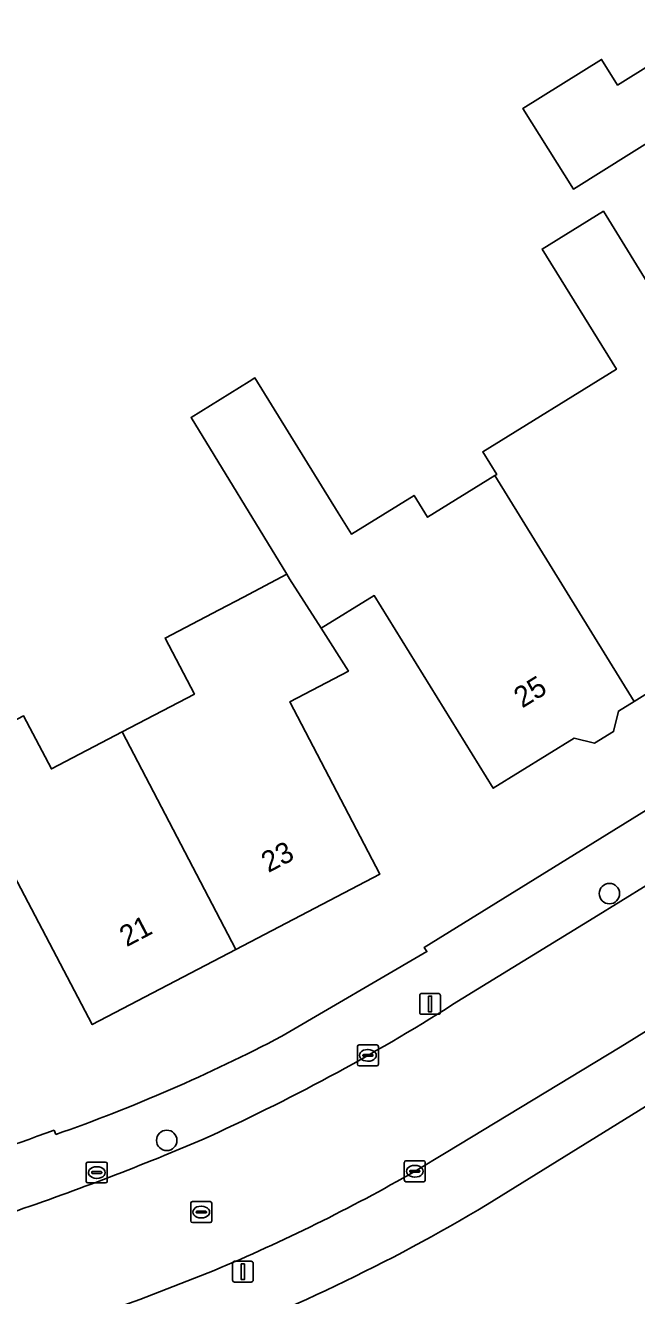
# Model space of a CAD drawing. Extents: x 161347 to 161881, y 382161 to 382804.
# Drawn here: x 161600.2 to 161629.5, y 382271.6 to 382332.5 of the extents above; entities that cross this region are included whole.
import ezdxf

# ---------------------------------------------------------------- set-up
doc = ezdxf.new("R2010")
doc.units = 0
for name, color, linetype in [('IMGEO_Boom', 7, 'Continuous'), ('IMGEO_Brandkraan', 7, 'Continuous'), ('IMGEO_Erf', 7, 'Continuous'), ('IMGEO_Kolk', 7, 'Continuous'), ('IMGEO_Lichtmast', 7, 'Continuous'), ('IMGEO_Pand', 7, 'Continuous'), ('IMGEO_Pand_nummerreeks', 7, 'Continuous'), ('IMGEO_Rijbaan_lokaal_open', 7, 'Continuous'), ('IMGEO_Rioolput', 7, 'Continuous'), ('IMGEO_Voetpad_open', 7, 'Continuous')]:
    doc.layers.add(name, color=color, linetype=linetype)

msp = doc.modelspace()

# ---------------------------------------------------------------- linework, layer by layer
at = {"layer": 'IMGEO_Boom'}
for centre in [(161628.212, 382290.895), (161606.995, 382279.062)]:
    msp.add_circle(centre, 0.489, dxfattribs=at)
at = {"layer": 'IMGEO_Brandkraan'}
for p, q in [((161603.141, 382277.094), (161603.141, 382277.946)), ((161603.216, 382278.02), (161604.068, 382278.02)), ((161603.629, 382277.8), (161603.654, 382277.8)), ((161604.142, 382277.946), (161604.142, 382277.094)), ((161603.4, 382277.514), (161603.4, 382277.526)), ((161603.838, 382277.477), (161603.44, 382277.477)), ((161603.443, 382277.563), (161603.841, 382277.563)), ((161603.652, 382277.24), (161603.627, 382277.24)), ((161603.884, 382277.526), (161603.884, 382277.514)), ((161604.068, 382277.02), (161603.216, 382277.02))]:
    msp.add_line(p, q, dxfattribs=at)
for points in [[(161603.141, 382277.094), (161603.141, 382277.946)], [(161603.216, 382278.02), (161604.068, 382278.02)], [(161604.142, 382277.946), (161604.142, 382277.094)], [(161604.068, 382277.02), (161603.216, 382277.02)]]:
    msp.add_lwpolyline(points, dxfattribs=at)
for centre, radius, start, end in [((161603.218, 382277.944), 0.0765, 91.55205, 178.44795), ((161603.218, 382277.944), 0.0765, 91.55205, 178.44795), ((161604.066, 382277.944), 0.0765, 1.55205, 88.44795), ((161604.066, 382277.944), 0.0765, 1.55205, 88.44795), ((161603.44, 382277.523), 0.0403, 85.87752, 175.75265), ((161603.437, 382277.513), 0.0366, 178.93798, 274.71019), ((161603.841, 382277.52), 0.043, 264.86636, 352.45326), ((161603.845, 382277.525), 0.0386, 1.73085, 96.63898), ((161603.218, 382277.096), 0.0765, 181.55205, 268.44795), ((161603.218, 382277.096), 0.0765, 181.55205, 268.44795), ((161604.066, 382277.096), 0.0765, 271.55205, 358.44795), ((161604.066, 382277.096), 0.0765, 271.55205, 358.44795)]:
    msp.add_arc(centre, radius, start, end, dxfattribs=at)
for centre, major_axis, ratio, start_param, end_param in [((161603.628, 382277.52), (-0.387, 0.002), 0.722429, 4.712389, 7.853982), ((161603.653, 382277.52), (-0.39, 0.002), 0.717154, 1.570796, 4.712389)]:
    msp.add_ellipse(centre, major_axis=major_axis, ratio=ratio, start_param=start_param, end_param=end_param, dxfattribs=at)
at = {"layer": 'IMGEO_Erf'}
msp.add_lwpolyline([(161624.069, 382328.546), (161627.833, 382330.897), (161628.603, 382329.665), (161633.186, 382332.528), (161634.831, 382329.9), (161626.488, 382324.676)], close=True, dxfattribs=at)
for points in [[(161600.138, 382299.417), (161601.468, 382296.877), (161604.858, 382298.652), (161608.324, 382300.466), (161606.919, 382303.151), (161609.508, 382304.506), (161610.671, 382305.115), (161612.756, 382306.206), (161608.161, 382313.731), (161610.943, 382315.45), (161611.22, 382315.621), (161615.211, 382309.16), (161615.843, 382308.136), (161618.847, 382309.992), (161619.493, 382308.946), (161622.718, 382310.938), (161622.812, 382310.996), (161622.141, 382312.082), (161628.545, 382316.037), (161624.985, 382321.799), (161627.927, 382323.616), (161630.537, 382319.392)], [(161612.505, 382284.052), (161619.461, 382288.113), (161619.333, 382288.314), (161666.754, 382317.654)], [(161714.958, 382287.913), (161711.315, 382289.649), (161703.155, 382293.259), (161697.545, 382295.944), (161686.732, 382302.424), (161677.151, 382309.804), (161671.693, 382306.549), (161622.353, 382275.985)], [(161630.161, 382300.586), (161629.4, 382300.115), (161628.639, 382299.645), (161628.408, 382298.667), (161627.502, 382298.107), (161626.515, 382298.341), (161622.646, 382295.951), (161616.941, 382305.186), (161614.4, 382303.617), (161615.706, 382301.563), (161612.889, 382300.089), (161617.212, 382291.832), (161610.315, 382288.222), (161603.422, 382284.613), (161599.158, 382292.758)], [(161601.607, 382279.553), (161601.675, 382279.343)]]:
    msp.add_lwpolyline(points, dxfattribs=at)
for centre, radius, start, end in [((161575, 382355.5), 80.694, 289.30356, 297.69628), ((161567.904, 382371.042), 97.5, 282.06729, 290.22306), ((161578.493, 382349.06), 85.227, 289.88576, 300.97211)]:
    msp.add_arc(centre, radius, start, end, dxfattribs=at)
at = {"layer": 'IMGEO_Kolk'}
for p, q in [((161616.137, 382282.712), (161616.137, 382283.564)), ((161616.212, 382283.638), (161617.064, 382283.638)), ((161616.625, 382283.418), (161616.65, 382283.418)), ((161617.138, 382283.564), (161617.138, 382282.712)), ((161616.396, 382283.132), (161616.396, 382283.144)), ((161616.834, 382283.095), (161616.436, 382283.095)), ((161616.439, 382283.181), (161616.837, 382283.181)), ((161616.648, 382282.858), (161616.623, 382282.858)), ((161616.88, 382283.144), (161616.88, 382283.132)), ((161617.064, 382282.638), (161616.212, 382282.638)), ((161618.382, 382277.154), (161618.382, 382278.006)), ((161618.457, 382278.08), (161619.309, 382278.08)), ((161618.87, 382277.86), (161618.895, 382277.86)), ((161619.383, 382278.006), (161619.383, 382277.154)), ((161618.641, 382277.574), (161618.641, 382277.586)), ((161619.079, 382277.537), (161618.681, 382277.537)), ((161618.684, 382277.623), (161619.082, 382277.623)), ((161618.893, 382277.3), (161618.868, 382277.3)), ((161619.125, 382277.586), (161619.125, 382277.574)), ((161619.309, 382277.08), (161618.457, 382277.08))]:
    msp.add_line(p, q, dxfattribs=at)
for points in [[(161616.137, 382282.712), (161616.137, 382283.564)], [(161616.212, 382283.638), (161617.064, 382283.638)], [(161617.138, 382283.564), (161617.138, 382282.712)], [(161617.064, 382282.638), (161616.212, 382282.638)], [(161618.382, 382277.154), (161618.382, 382278.006)], [(161618.457, 382278.08), (161619.309, 382278.08)], [(161619.383, 382278.006), (161619.383, 382277.154)], [(161619.309, 382277.08), (161618.457, 382277.08)]]:
    msp.add_lwpolyline(points, dxfattribs=at)
for centre, radius, start, end in [((161616.214, 382283.562), 0.0765, 91.55205, 178.44795), ((161616.214, 382283.562), 0.0765, 91.55205, 178.44795), ((161617.062, 382283.562), 0.0765, 1.55205, 88.44795), ((161617.062, 382283.562), 0.0765, 1.55205, 88.44795), ((161616.214, 382282.714), 0.0765, 181.55205, 268.44795), ((161616.214, 382282.714), 0.0765, 181.55205, 268.44795), ((161616.436, 382283.141), 0.0403, 85.87752, 175.75265), ((161616.433, 382283.131), 0.0366, 178.93798, 274.71019), ((161616.837, 382283.138), 0.043, 264.86636, 352.45326), ((161616.841, 382283.143), 0.0386, 1.73085, 96.63898), ((161617.062, 382282.714), 0.0765, 271.55205, 358.44795), ((161617.062, 382282.714), 0.0765, 271.55205, 358.44795), ((161618.459, 382278.004), 0.0765, 91.55205, 178.44795), ((161618.459, 382278.004), 0.0765, 91.55205, 178.44795), ((161619.307, 382278.004), 0.0765, 1.55205, 88.44795), ((161619.307, 382278.004), 0.0765, 1.55205, 88.44795), ((161618.681, 382277.583), 0.0403, 85.87752, 175.75265), ((161618.678, 382277.573), 0.0366, 178.93798, 274.71019), ((161619.082, 382277.58), 0.043, 264.86636, 352.45326), ((161619.086, 382277.585), 0.0386, 1.73085, 96.63898), ((161618.459, 382277.156), 0.0765, 181.55205, 268.44795), ((161618.459, 382277.156), 0.0765, 181.55205, 268.44795), ((161619.307, 382277.156), 0.0765, 271.55205, 358.44795), ((161619.307, 382277.156), 0.0765, 271.55205, 358.44795)]:
    msp.add_arc(centre, radius, start, end, dxfattribs=at)
for centre, major_axis, ratio, start_param, end_param in [((161616.624, 382283.138), (-0.387, 0.002), 0.722429, 4.712389, 7.853982), ((161616.649, 382283.138), (-0.39, 0.002), 0.717154, 1.570796, 4.712389), ((161618.869, 382277.58), (-0.387, 0.002), 0.722429, 4.712389, 7.853982), ((161618.894, 382277.58), (-0.39, 0.002), 0.717154, 1.570796, 4.712389)]:
    msp.add_ellipse(centre, major_axis=major_axis, ratio=ratio, start_param=start_param, end_param=end_param, dxfattribs=at)
at = {"layer": 'IMGEO_Lichtmast'}
for p, q in [((161619.118, 382285.207), (161619.118, 382286.007)), ((161619.118, 382286.007), (161619.118, 382285.207)), ((161619.218, 382286.107), (161620.008, 382286.107)), ((161620.008, 382286.107), (161619.218, 382286.107)), ((161620.108, 382286.007), (161620.108, 382285.207)), ((161620.108, 382285.207), (161620.108, 382286.007)), ((161620.008, 382285.107), (161619.218, 382285.107)), ((161619.218, 382285.107), (161620.008, 382285.107)), ((161610.148, 382272.363), (161610.148, 382273.163)), ((161610.148, 382273.163), (161610.148, 382272.363)), ((161610.248, 382273.263), (161611.038, 382273.263)), ((161611.038, 382273.263), (161610.248, 382273.263)), ((161611.138, 382273.163), (161611.138, 382272.363)), ((161611.138, 382272.363), (161611.138, 382273.163)), ((161611.038, 382272.263), (161610.248, 382272.263)), ((161610.248, 382272.263), (161611.038, 382272.263))]:
    msp.add_line(p, q, dxfattribs=at)
for points in [[(161619.538, 382285.982), (161619.688, 382285.982), (161619.688, 382285.232), (161619.538, 382285.232), (161619.538, 382285.982)], [(161610.568, 382273.138), (161610.718, 382273.138), (161610.718, 382272.388), (161610.568, 382272.388), (161610.568, 382273.138)]]:
    msp.add_lwpolyline(points, dxfattribs=at)
for centre, start, end in [((161619.218, 382286.007), 90, 180), ((161619.218, 382286.007), 90, 180), ((161620.008, 382286.007), 0, 90), ((161620.008, 382286.007), 360, 90), ((161619.218, 382285.207), 180, 270), ((161619.218, 382285.207), 180, 270), ((161620.008, 382285.207), 270, 0), ((161620.008, 382285.207), 270, 0), ((161610.248, 382273.163), 90, 180), ((161610.248, 382273.163), 90, 180), ((161611.038, 382273.163), 0, 90), ((161611.038, 382273.163), 360, 90), ((161610.248, 382272.363), 180, 270), ((161610.248, 382272.363), 180, 270), ((161611.038, 382272.363), 270, 0), ((161611.038, 382272.363), 270, 0)]:
    msp.add_arc(centre, 0.1, start, end, dxfattribs=at)
at = {"layer": 'IMGEO_Pand'}
for points in [[(161634.831, 382329.9), (161633.186, 382332.528), (161628.603, 382329.665), (161627.833, 382330.897), (161624.069, 382328.546), (161626.488, 382324.676)], [(161629.4, 382300.115), (161630.161, 382300.586), (161631.199, 382300.341), (161632.107, 382300.902), (161632.349, 382301.927), (161636.293, 382304.363), (161630.612, 382313.56), (161633.165, 382315.138), (161630.537, 382319.392), (161627.927, 382323.616), (161624.985, 382321.799), (161628.545, 382316.037), (161622.141, 382312.082), (161622.812, 382310.996), (161622.718, 382310.938)], [(161622.718, 382310.938), (161619.493, 382308.946), (161618.847, 382309.992), (161615.843, 382308.136), (161615.211, 382309.16), (161611.22, 382315.621), (161610.943, 382315.45), (161608.161, 382313.731), (161612.756, 382306.206), (161612.885, 382305.994), (161614.4, 382303.617), (161616.941, 382305.186), (161622.646, 382295.951), (161626.515, 382298.341), (161627.502, 382298.107), (161628.408, 382298.667), (161628.639, 382299.645), (161629.4, 382300.115)], [(161604.858, 382298.652), (161601.468, 382296.877), (161600.138, 382299.417), (161596.981, 382297.765), (161596.192, 382299.272), (161596.799, 382299.591), (161596.949, 382299.67), (161595.561, 382303.682), (161594.602, 382306.453), (161591.747, 382305.538), (161592.724, 382302.76), (161594.929, 382296.386), (161596.664, 382291.452), (161599.158, 382292.758), (161603.422, 382284.613), (161610.315, 382288.222)], [(161614.4, 382303.617), (161612.885, 382305.994), (161612.756, 382306.206), (161610.671, 382305.115), (161609.508, 382304.506), (161606.919, 382303.151), (161608.324, 382300.466), (161604.858, 382298.652), (161610.315, 382288.222), (161617.212, 382291.832), (161612.889, 382300.089), (161615.706, 382301.563)]]:
    msp.add_lwpolyline(points, close=True, dxfattribs=at)
at = {"layer": 'IMGEO_Rijbaan_lokaal_open'}
for points in [[(161618.896, 382277.584), (161620.383, 382278.485), (161628.112, 382283.168), (161628.72, 382283.536), (161633.128, 382286.258), (161630.045, 382291.331), (161627.466, 382289.739), (161620.698, 382285.57)], [(161608.681, 382279.087), (161606.868, 382278.333)], [(161601.914, 382270.088), (161605.711, 382271.429), (161609.273, 382272.828)]]:
    msp.add_lwpolyline(points, dxfattribs=at)
for centre, radius, start, end in [((161568.041, 382368.797), 98.486, 294.37126, 302.32119), ((161556.15, 382402.863), 134.462, 287.9045, 292.15977), ((161576.222, 382351.814), 85.622, 292.70624, 299.89393)]:
    msp.add_arc(centre, radius, start, end, dxfattribs=at)
at = {"layer": 'IMGEO_Rioolput'}
for p, q in [((161608.151, 382275.198), (161608.151, 382276.05)), ((161608.226, 382276.124), (161609.078, 382276.124)), ((161609.152, 382276.05), (161609.152, 382275.198)), ((161608.41, 382275.618), (161608.41, 382275.63)), ((161608.848, 382275.581), (161608.45, 382275.581)), ((161608.453, 382275.667), (161608.851, 382275.667)), ((161608.662, 382275.344), (161608.637, 382275.344)), ((161608.639, 382275.904), (161608.664, 382275.904)), ((161608.894, 382275.63), (161608.894, 382275.618)), ((161609.078, 382275.124), (161608.226, 382275.124))]:
    msp.add_line(p, q, dxfattribs=at)
for points in [[(161608.151, 382275.198), (161608.151, 382276.05)], [(161608.226, 382276.124), (161609.078, 382276.124)], [(161609.152, 382276.05), (161609.152, 382275.198)], [(161609.078, 382275.124), (161608.226, 382275.124)]]:
    msp.add_lwpolyline(points, dxfattribs=at)
for centre, radius, start, end in [((161608.228, 382276.048), 0.0765, 91.55205, 178.44795), ((161608.228, 382276.048), 0.0765, 91.55205, 178.44795), ((161609.076, 382276.048), 0.0765, 1.55205, 88.44795), ((161609.076, 382276.048), 0.0765, 1.55205, 88.44795), ((161608.45, 382275.627), 0.0403, 85.87752, 175.75265), ((161608.447, 382275.617), 0.0366, 178.93798, 274.71019), ((161608.851, 382275.624), 0.043, 264.86636, 352.45326), ((161608.855, 382275.629), 0.0386, 1.73085, 96.63898), ((161608.228, 382275.2), 0.0765, 181.55205, 268.44795), ((161608.228, 382275.2), 0.0765, 181.55205, 268.44795), ((161609.076, 382275.2), 0.0765, 271.55205, 358.44795), ((161609.076, 382275.2), 0.0765, 271.55205, 358.44795)]:
    msp.add_arc(centre, radius, start, end, dxfattribs=at)
for centre, major_axis, ratio, start_param, end_param in [((161608.638, 382275.624), (-0.387, 0.002), 0.722429, 4.712389, 7.853982), ((161608.663, 382275.624), (-0.39, 0.002), 0.717154, 1.570796, 4.712389)]:
    msp.add_ellipse(centre, major_axis=major_axis, ratio=ratio, start_param=start_param, end_param=end_param, dxfattribs=at)
at = {"layer": 'IMGEO_Voetpad_open'}
for points in [[(161620.698, 382285.57), (161627.466, 382289.739), (161630.045, 382291.331), (161632.48, 382292.857), (161634.126, 382293.868), (161639.777, 382297.347), (161639.517, 382297.769), (161649.9, 382304.17), (161650.157, 382303.754), (161650.804, 382304.153), (161666.523, 382313.889), (161668.184, 382314.902), (161666.754, 382317.654), (161619.333, 382288.314), (161619.461, 382288.113), (161612.505, 382284.052)], [(161671.693, 382306.549), (161677.151, 382309.804), (161675.035, 382312.158), (161661.309, 382303.664), (161653.759, 382298.992), (161645.583, 382293.956), (161641.382, 382291.368), (161637.303, 382288.856), (161635.555, 382287.777), (161633.128, 382286.258), (161628.72, 382283.536), (161628.112, 382283.168), (161620.383, 382278.485), (161618.896, 382277.584)], [(161622.353, 382275.985), (161671.693, 382306.549)], [(161601.675, 382279.343), (161601.607, 382279.553)], [(161606.868, 382278.333), (161608.681, 382279.087)], [(161609.273, 382272.828), (161605.711, 382271.429), (161601.914, 382270.088)]]:
    msp.add_lwpolyline(points, dxfattribs=at)
for centre, radius, start, end in [((161568.041, 382368.797), 98.486, 294.37126, 302.32119), ((161575, 382355.5), 80.694, 289.30356, 297.69628), ((161567.904, 382371.042), 97.5, 282.06729, 290.22306), ((161556.15, 382402.863), 134.462, 287.9045, 292.15977), ((161576.222, 382351.814), 85.622, 292.70624, 299.89393), ((161578.493, 382349.06), 85.227, 289.88576, 300.97211)]:
    msp.add_arc(centre, radius, start, end, dxfattribs=at)

# ---------------------------------------------------------------- texts
at = {"layer": 'IMGEO_Pand_nummerreeks'}
for s, rotation, p in [('25', 31.65019, (161624.032, 382299.766)), ('23', 27.63375, (161611.865, 382291.877)), ('21', 27.63375, (161605.07, 382288.32))]:
    msp.add_text(s, height=1, rotation=rotation, dxfattribs=at).set_placement(p)

doc.saveas('drawing.dxf')
